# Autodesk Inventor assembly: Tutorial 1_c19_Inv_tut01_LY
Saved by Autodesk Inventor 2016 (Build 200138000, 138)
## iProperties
Created: 2015-04
Part Number: Tutorial 1_c19_Inv_tut01_LY
Document SubType Name: Assembly
Designer: Sandeep
Author: Sandeep
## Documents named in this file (2)
- C:\Autodesk Inventor 2016\c19\Tutorial 1_c19_Inv_tut01_LY.iam
- C:\Autodesk Inventor 2016\c19\Tutorial 1_c19_Inv_tut01_PZ.iam
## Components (1 placed, 1 different names)
1. Tutorial 1_c19_Inv_tut01_PZ:1 [sub-assembly] — Flush:1, Flush:2, Flush:3
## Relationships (3: Flush 3)
- Flush:1: Tutorial 1_c19_Inv_tut01_PZ:1
- Flush:2: Tutorial 1_c19_Inv_tut01_PZ:1
- Flush:3: Tutorial 1_c19_Inv_tut01_PZ:1
